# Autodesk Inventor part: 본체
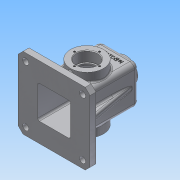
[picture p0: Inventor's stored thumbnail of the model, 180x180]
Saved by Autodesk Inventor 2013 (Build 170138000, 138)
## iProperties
Created: 2018-10
Part Number: 본체
Material: 알루미늄 6061
Document SubType Name: Modeling
Designer: Administrator
Density: 2.71 g/cm^3
Mass: 801.106 g
Surface Area: 898.447 cm^2
Volume: 295.611 cm^3
Author: Administrator
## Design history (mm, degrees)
node "작업 평면1"
sketch "스케치1"
  geometry: L1 (-32.5, 32.5)-(32.5, 32.5); L2 (32.5, 32.5)-(32.5, -32.5); L3 (32.5, -32.5)-(-32.5, -32.5); L4 (-32.5, -32.5)-(-32.5, 32.5); L5 (-32.5, 32.5)-(32.5, -32.5); L6 (32.5, 32.5)-(-32.5, -32.5); 1 further point
  constraints: 12 end point, 2 midpoint, 2 parallel, 1 horizontal, 1 perpendicular
  dimensions: "d1" = 65 distance of L2.end L3.end; "d2" = 65 distance of L1.end L2.end
extrude "돌출1" new body sketch "스케치1" distance "d3" = 110; taper "d4" = 0 deg
feature "쉘1" dims "d5" = 5
fillet "모깎기3" dims "d8" = 3
fillet "모깎기4" dims "d9" = 3
sketch "스케치5"
  geometry: C1 r 27.5 at (32.5, 55); 1 further point
  constraints: 1 centre point, 1 coincident
  dimensions: "d19" = 55 diameter of C1
extrude "돌출5" join sketch "스케치5" distance "d20" = 15; taper "d21" = 0 deg
sketch "스케치6"
  geometry: C1 r 27.5 at (0, 0) reference; C2 r 17.5 at (0, 0)
  constraints: 1 centre point, 1 coincident
  dimensions: "d22" = 35 diameter of C2
extrude "돌출6" cut sketch "스케치6" distance "d23" = 17; taper "d24" = 0 deg
sketch "스케치7"
  geometry: C1 r 17.5 at (0, 0) reference; C2 r 15 at (0, 0)
  constraints: 1 centre point, 1 coincident
  dimensions: "d25" = 30 diameter of C2
extrude "돌출7" cut sketch "스케치7" distance "d26" = 3; taper "d27" = 0 deg
fillet "모깎기5" dims "d28" = 8
fillet "모깎기6" dims "d29" = 8
fillet "모깎기7" dims "d30" = 0.3
chamfer "모따기1" distance "d31" = 1; stored, may be unused: second distance "d32" = 2, angle "d33" = 45 deg
node "작업 평면2"
sketch "스케치9"
  geometry: C1 r 20 at (0, 0); 1 further point
  constraints: 1 centre point, 1 coincident
  dimensions: "d35" = 40 diameter of C1
extrude "돌출8" join sketch "스케치9" stored distance "d36" = 3; taper "d37" = 7 deg
sketch "스케치10"
  geometry: C1 r 20 at (0, 0) reference; 1 further point
  constraints: 1 coincident
hole "구멍1" sketch "스케치10" at (0, 0) diameter "d38" = 22.835; stored, may be unused: countersink angle "d42" = 90 deg, drill point angle "d44" = 118 deg; dims "d39" = 20, "d40" = 4, "d41" = 2, "d43" = 8
sketch "스케치11"
  geometry: L1 (-24.5, -32.5)-(24.5, -32.5) reference; L2 (32.5, -24.5)-(32.5, 24.5) reference; L3 (24.5, 32.5)-(-24.5, 32.5) reference; L4 (-32.5, 24.5)-(-32.5, -24.5) reference; L5 (-60, 60)-(60, 60); L6 (60, 60)-(60, -60); L7 (60, -60)-(-60, -60); L8 (-60, -60)-(-60, 60); L9 (-60, 60)-(60, -60); L10 (60, 60)-(-60, -60); A1 r 8 centre (-24.5, -24.5) between (-32.5, -24.5) and (-24.5, -32.5) reference; A2 r 8 centre (24.5, -24.5) between (24.5, -32.5) and (32.5, -24.5) reference; A3 r 8 centre (24.5, 24.5) between (32.5, 24.5) and (24.5, 32.5) reference; A4 r 8 centre (-24.5, 24.5) between (-24.5, 32.5) and (-32.5, 24.5) reference; 1 further point
  constraints: 12 end point, 2 midpoint, 2 parallel, 1 horizontal, 1 perpendicular
  dimensions: "d45" = 120 distance of L6.end L7.end; "d46" = 120 distance of L5.end L6.end
extrude "돌출9" join sketch "스케치11" distance "d47" = 10; taper "d48" = 0 deg
chamfer "모따기2" distance "d49" = 8; stored, may be unused: second distance "d50" = 2, angle "d51" = 45 deg
sketch "스케치12"
  geometry: L1 (-60, 52)-(-60, -52) reference; L2 (52, 60)-(-52, 60) reference; C1 r 5 at (-47.5, 47.5); C2 r 5 at (47.5, 47.5); 1 further point
  constraints: 2 centre point, 1 horizontal alignment
  dimensions: "d52" = 95 distance of C2.centre C1.centre; "d54" = 10 diameter of C1; "d55" = 10 diameter of C2; "d56" = 12.5 distance from line of L2 C2.centre; "d57" = 12.5 distance from line of L1 C1.centre
extrude "돌출10" cut sketch "스케치12" stored distance "d58" = 10; taper "d59" = 0 deg
sketch "스케치13"
  geometry: L1 (-35.591, 25.373)-(-48, -45); L2 (-27.5, 47)-(-27.5, -55) reference; L3 (-27.5, -55)-(-60, -55) reference; L4 (-60, -55)-(-60, -45) reference; L5 (-60, -45)-(-32.5, -45) reference; L6 (-32.5, -45)-(-32.5, 47) reference; L7 (-24.5, 55)-(-21.228, 55) reference; L8 (-21.228, 55)-(-20, 65) reference; L9 (-20, 65)-(-11.418, 65) reference; L10 (-11.418, 65)-(-11.418, 50) reference; L11 (-11.418, 50)-(-24.5, 50) reference; L12 (24.5, 50)-(11.418, 50) reference; L13 (11.418, 50)-(11.418, 65) reference; L14 (11.418, 65)-(20, 65) reference; L15 (20, 65)-(21.228, 55) reference; L16 (21.228, 55)-(24.5, 55) reference; L17 (32.5, 47)-(32.5, -45) reference; L18 (32.5, -45)-(60, -45) reference; L19 (60, -45)-(60, -55) reference; L20 (60, -55)-(27.5, -55) reference; L21 (27.5, -55)-(27.5, 47) reference; L22 (-52, -45)-(-60, -45) reference; L23 (-52, -45)-(52, -45) reference; A1 r 3 centre (-24.5, 47) between (-24.5, 50) and (-27.5, 47) reference; A2 r 8 centre (-24.5, 47) between (-24.5, 55) and (-32.5, 47) reference; A3 r 3 centre (24.5, 47) between (27.5, 47) and (24.5, 50) reference; A4 r 8 centre (24.5, 47) between (32.5, 47) and (24.5, 55) reference; 1 further point
  constraints: 2 end point, 1 point on line
  dimensions: "d60" = 12 distance from line of L1.end L4; "d61" = 10 deg angle of L4 L1
feature "리브1" sketch "스케치13" dims "d62" = 1, "d63" = 10, "d64" = 0, "d65" = 0, "d66" = 1, "d67" = 1
sketch "스케치14"
  geometry: L1 (-30.841, 42.5)-(-45, 42.5); L2 (-17.5, -46.5)-(-18.5, -47.5) reference; L3 (-18.5, -47.5)-(-27.5, -47.5) reference; L4 (-27.5, -47.5)-(-27.5, -32.5) reference; L5 (-27.5, -32.5)-(-45, -32.5) reference; L6 (-45, -32.5)-(-45, -60) reference; L7 (-45, -60)-(-55, -60) reference; L8 (-55, -60)-(-55, -27.5) reference; L9 (-55, -27.5)-(-15, -27.5) reference; L10 (-15, -27.5)-(-15, -30.5) reference; L11 (-15, -30.5)-(-17.2, -30.5) reference; L12 (-17.5, -30.8)-(-17.5, -46.5) reference; L13 (18.5, -47.5)-(17.5, -46.5) reference; L14 (17.5, -46.5)-(17.5, -30.8) reference; L15 (17.2, -30.5)-(15, -30.5) reference; L16 (15, -30.5)-(15, -27.5) reference; L17 (15, -27.5)-(47, -27.5) reference; L18 (50, -24.5)-(50, -11.418) reference; L19 (50, -11.418)-(65, -11.418) reference; L20 (65, -11.418)-(65, -20) reference; L21 (65, -20)-(55, -21.228) reference; L22 (55, -21.228)-(55, -24.5) reference; L23 (47, -32.5)-(27.5, -32.5) reference; L24 (27.5, -32.5)-(27.5, -47.5) reference; L25 (27.5, -47.5)-(18.5, -47.5) reference; L26 (17.5, 46.5)-(18.5, 47.5) reference; L27 (18.5, 47.5)-(27.5, 47.5) reference; L28 (27.5, 47.5)-(27.5, 32.5) reference; L29 (27.5, 32.5)-(47, 32.5) reference; L30 (55, 24.5)-(55, 21.228) reference; L31 (55, 21.228)-(65, 20) reference; L32 (65, 20)-(65, 11.418) reference; L33 (65, 11.418)-(50, 11.418) reference; L34 (50, 11.418)-(50, 24.5) reference; L35 (47, 27.5)-(15, 27.5) reference; L36 (15, 27.5)-(15, 30.5) reference; L37 (15, 30.5)-(17.2, 30.5) reference; L38 (17.5, 30.8)-(17.5, 46.5) reference; L39 (-18.5, 47.5)-(-17.5, 46.5) reference; L40 (-17.5, 46.5)-(-17.5, 30.8) reference; L41 (-17.2, 30.5)-(-15, 30.5) reference; L42 (-15, 30.5)-(-15, 27.5) reference; L43 (-15, 27.5)-(-55, 27.5) reference; L44 (-55, 27.5)-(-55, 60) reference; L45 (-55, 60)-(-45, 60) reference; L46 (-45, 60)-(-45, 32.5) reference; L47 (-45, 32.5)-(-27.5, 32.5) reference; L48 (-27.5, 32.5)-(-27.5, 47.5) reference; L49 (-27.5, 47.5)-(-18.5, 47.5) reference; L50 (-45, 52)-(-45, -52) reference; A1 r 0.3 centre (-17.2, -30.8) between (-17.2, -30.5) and (-17.5, -30.8) reference; A2 r 0.3 centre (17.2, -30.8) between (17.5, -30.8) and (17.2, -30.5) reference; A3 r 3 centre (47, -24.5) between (47, -27.5) and (50, -24.5) reference; A4 r 8 centre (47, -24.5) between (47, -32.5) and (55, -24.5) reference; A5 r 8 centre (47, 24.5) between (55, 24.5) and (47, 32.5) reference; A6 r 3 centre (47, 24.5) between (50, 24.5) and (47, 27.5) reference; A7 r 0.3 centre (17.2, 30.8) between (17.2, 30.5) and (17.5, 30.8) reference; A8 r 0.3 centre (-17.2, 30.8) between (-17.5, 30.8) and (-17.2, 30.5) reference; 1 further point
  constraints: 2 end point, 1 horizontal, 1 point on line
  dimensions: "d68" = 15 distance between parallel lines of L43 L1
feature "리브2" sketch "스케치14" dims "d69" = 1, "d70" = 6, "d71" = 0, "d72" = 0, "d73" = 1, "d74" = 1
fillet "모깎기8" dims "d75" = 3
fillet "모깎기9" dims "d76" = 3
fillet "모깎기10" dims "d77" = 1
fillet "모깎기11" dims "d78" = 3
sketch "스케치15"
  geometry: C1 r 18.5 at (0, 0) reference; 1 further point
  constraints: 1 vertical alignment
  dimensions: "d79" = 21 distance of C1.centre point (0, 21)
hole "구멍2" sketch "스케치15" at (0, 21) diameter "d80" = 3.242; stored, may be unused: countersink angle "d84" = 90 deg, drill point angle "d86" = 118 deg; dims "d81" = 8, "d82" = 4, "d83" = 2, "d85" = 10
fillet "모깎기12" dims "d90" = 3
sketch "스케치16"
  geometry: L1 (4.5, 18)-(44.5, 18) reference; L2 (-8, 0)-(-8, -91) reference; 1 further point
  constraints: 1 other
  dimensions: "d92" = 26 distance from line of L1 point (24.5, -8); "d93" = 32.5 distance from line of L2 point (24.5, -8)
feature "엠보싱1" sketch "스케치16" dims "d94" = 0.5, "d95" = 0
node "솔리드1"
mirror "대칭2"
mirror "대칭3"
mirror "대칭4"
mirror "대칭5"
pattern_circular "원형 패턴1" dims angle "d88" = 360 deg
mirror "대칭6"
node "절단 모서리 투영1"
node "절단 모서리 투영2"
other parameters: "d0" = -55
